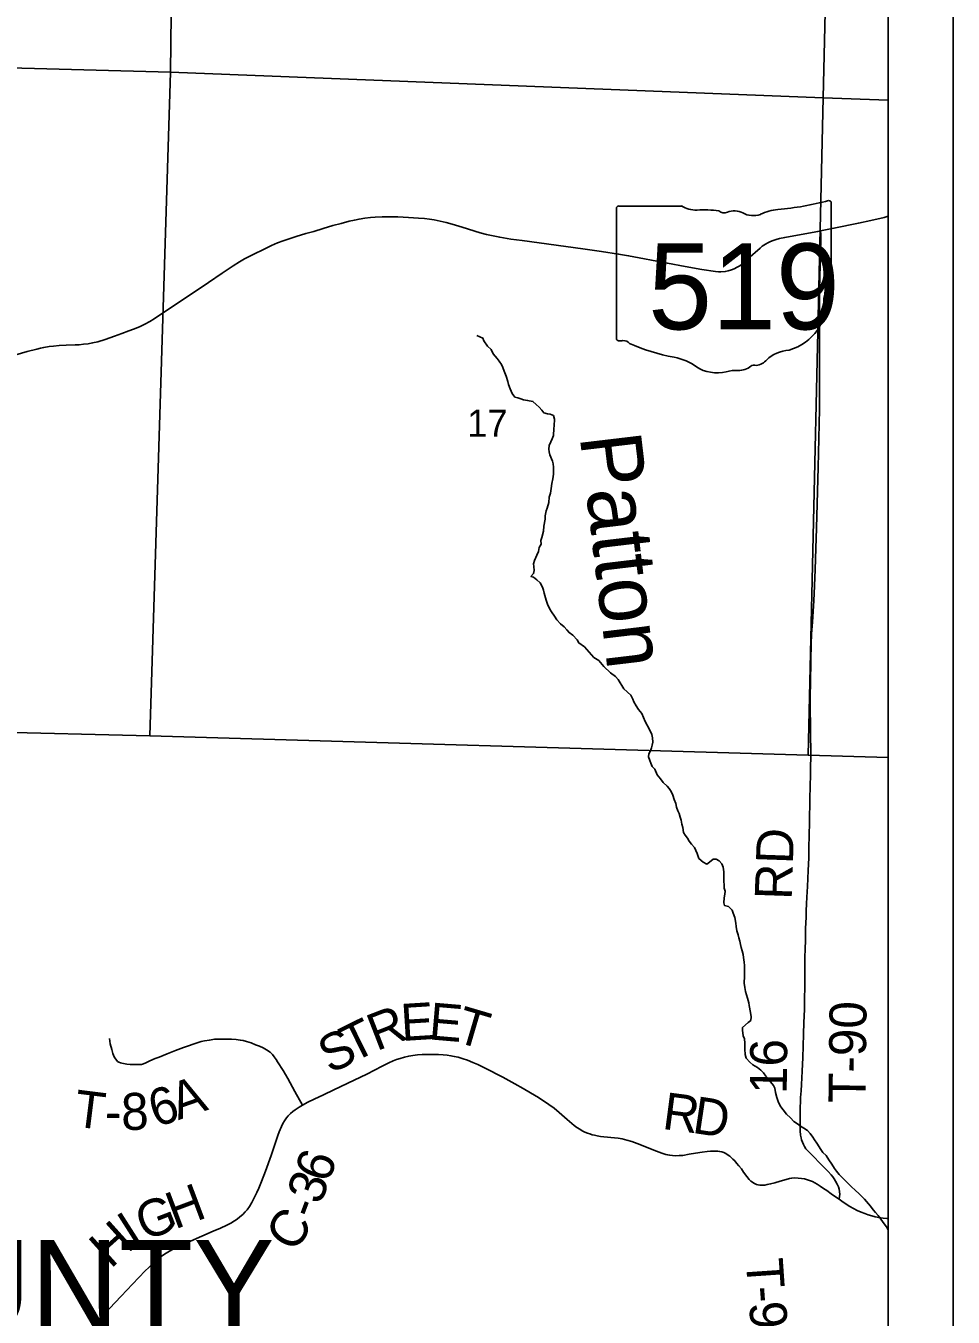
# Model space of a CAD drawing. Extents: x 0 to 34, y 0 to 22.
# Drawn here: x 8.076 to 9.5, y 16.635 to 18.617 of the extents above; entities that cross this region are included whole.
import ezdxf

# ---------------------------------------------------------------- set-up
doc = ezdxf.new("R2010")
doc.units = 0
for name, color, linetype in [('GM_X_Corporation', 7, 'Continuous'), ('GM_X_County_Road', 7, 'Continuous'), ('GM_X_County_Road_Text', 7, 'Continuous'), ('GM_X_Minor_River', 7, 'Continuous'), ('GM_X_Minor_River_Text', 7, 'Continuous'), ('GM_X_Section_Text', 7, 'Continuous'), ('GM_X_State_Location', 7, 'Continuous'), ('GM_X_State_Route', 7, 'Continuous'), ('GM_X_State_Shield', 7, 'Continuous'), ('GM_X_Township_Road', 7, 'Continuous'), ('GM_X_Township_Road_Text', 7, 'Continuous'), ('SH_Data', 7, 'Continuous'), ('SH_Text', 7, 'Continuous')]:
    doc.layers.add(name, color=color, linetype=linetype)

msp = doc.modelspace()

# ---------------------------------------------------------------- linework, layer by layer
at = {"layer": 'GM_X_Corporation'}
for points in [[(9.4, 16.4853), (9.4, 20.4), (2.6, 20.4), (2.6, 16.6918), (3.1555, 16.6686), (3.1684, 16.6682), (4.0515, 16.6368), (4.1011, 16.6362), (4.1867, 16.6352), (4.5473, 16.6256), (4.6351, 16.6229), (5.4202, 16.5982), (6.0834, 16.5816), (6.2194, 16.578), (8.0963, 16.5226), (9.09, 16.4927)], [(9.4, 16.4853), (9.4, 20.4), (6.2895, 20.4), (6.2595, 19.6124), (6.2942, 19.6131), (6.2926, 19.1539), (6.292, 18.5898), (6.2786, 18.5898), (6.2744, 18.4654), (6.2729, 18.2077), (6.2194, 16.578), (8.0963, 16.5226), (9.09, 16.4927)], [(8.2946, 19.5667), (8.3101, 19.5662), (8.2986, 18.5464), (7.291, 18.5737), (7.3046, 19.5855)], [(9.3157, 19.5601), (9.3252, 19.5587), (9.3006, 18.5069), (8.2986, 18.5464), (8.3101, 19.5662)], [(9.4, 18.5032), (9.4, 19.5563), (9.3252, 19.5587), (9.3006, 18.5069)], [(8.2986, 18.5464), (8.2669, 17.5271), (7.261, 17.5518), (7.291, 18.5737)], [(8.2986, 18.5464), (9.3006, 18.5069), (9.2775, 17.4976), (8.2669, 17.5271)], [(9.4, 17.4939), (9.4, 18.5032), (9.3006, 18.5069), (9.2775, 17.4976)]]:
    msp.add_lwpolyline(points, close=True, dxfattribs=at)
at = {"layer": 'GM_X_County_Road'}
msp.add_lwpolyline([(8.1832, 16.6253), (8.1961, 16.6386), (8.2229, 16.667), (8.2402, 16.6855), (8.2597, 16.7057), (8.2651, 16.711), (8.2723, 16.7179), (8.2779, 16.7229), (8.284, 16.7276), (8.2892, 16.7312), (8.2967, 16.7357), (8.3016, 16.7384), (8.3111, 16.743), (8.3289, 16.7513), (8.3467, 16.7589), (8.3641, 16.7665), (8.3752, 16.7713), (8.3851, 16.7758), (8.3912, 16.779), (8.3968, 16.7824), (8.4008, 16.7853), (8.4051, 16.7885), (8.4092, 16.7922), (8.4132, 16.7961), (8.4159, 16.7995), (8.4195, 16.8046), (8.4233, 16.8106), (8.427, 16.8177), (8.431, 16.8261), (8.4339, 16.8327), (8.4379, 16.8427), (8.444, 16.8586), (8.4528, 16.8827), (8.4591, 16.9014), (8.4633, 16.9136), (8.4653, 16.9191), (8.4687, 16.9273), (8.4709, 16.9318), (8.4735, 16.9362), (8.4767, 16.9406), (8.4793, 16.9437), (8.4827, 16.9473), (8.4862, 16.9503), (8.4899, 16.9531), (8.496, 16.9571), (8.5013, 16.9602), (8.5091, 16.9646), (8.5188, 16.9695), (8.5334, 16.9762), (8.5491, 16.9835), (8.5805, 16.9984), (8.5996, 17.0079), (8.6234, 17.0201), (8.6334, 17.0251), (8.6404, 17.0283), (8.6456, 17.0302), (8.6508, 17.032), (8.6574, 17.0339), (8.6641, 17.0354), (8.6707, 17.0365), (8.6774, 17.0373), (8.685, 17.0378), (8.693, 17.0379), (8.7097, 17.0377), (8.7172, 17.0373), (8.723, 17.0369), (8.7288, 17.0361), (8.7341, 17.035), (8.7401, 17.0336), (8.7479, 17.0314), (8.7542, 17.0293), (8.7628, 17.0257), (8.77, 17.0225), (8.7814, 17.017), (8.8084, 17.0029), (8.827, 16.9929), (8.8399, 16.9857), (8.8511, 16.9793), (8.8632, 16.9717), (8.879, 16.9612), (8.8872, 16.9553), (8.8952, 16.9487), (8.9072, 16.9382), (8.9181, 16.9291), (8.9224, 16.9259), (8.9267, 16.9231), (8.9306, 16.9209), (8.9345, 16.9189), (8.9385, 16.9172), (8.9423, 16.9159), (8.9458, 16.9148), (8.9496, 16.9138), (8.9536, 16.913), (8.9585, 16.9122), (8.9742, 16.9106), (8.9856, 16.9093), (8.992, 16.9083), (8.9989, 16.9066), (9.0066, 16.9042), (9.0151, 16.9012), (9.0266, 16.8968), (9.0403, 16.8911), (9.0529, 16.8863), (9.0589, 16.8844), (9.0617, 16.8838), (9.0649, 16.8832), (9.0693, 16.8827), (9.0741, 16.8825), (9.0792, 16.8826), (9.085, 16.883), (9.0946, 16.8847), (9.1046, 16.8866), (9.1144, 16.8881), (9.1222, 16.8892), (9.1273, 16.8895), (9.1321, 16.8897), (9.1356, 16.8895), (9.1386, 16.8893), (9.1413, 16.889), (9.1448, 16.8882), (9.148, 16.8872), (9.151, 16.8857), (9.1544, 16.8835), (9.1571, 16.8816), (9.1617, 16.8774), (9.1646, 16.8745), (9.1676, 16.8713), (9.1708, 16.8671), (9.1749, 16.8622), (9.1783, 16.8572), (9.1832, 16.8504), (9.187, 16.8461), (9.1894, 16.8436), (9.1917, 16.8417), (9.1939, 16.8403), (9.196, 16.8393), (9.1981, 16.8384), (9.2005, 16.8377), (9.203, 16.8373), (9.2107, 16.8374), (9.2146, 16.8381), (9.2197, 16.8393), (9.2263, 16.8411), (9.2342, 16.8435), (9.2437, 16.8462), (9.2486, 16.8475), (9.2522, 16.8482), (9.2567, 16.8485), (9.2618, 16.8482), (9.2673, 16.8477), (9.2716, 16.847), (9.2763, 16.8457), (9.2812, 16.8441), (9.2841, 16.8428), (9.2875, 16.8411), (9.2913, 16.8389), (9.2959, 16.8359), (9.301, 16.8323), (9.3059, 16.8289), (9.3128, 16.8239), (9.3224, 16.8171), (9.3248, 16.8156), (9.3291, 16.8125), (9.3342, 16.8091), (9.3412, 16.8046), (9.347, 16.8013), (9.3525, 16.7986), (9.3586, 16.7958), (9.3642, 16.7936), (9.3694, 16.7918), (9.3749, 16.79), (9.3805, 16.7886), (9.3858, 16.7875), (9.3927, 16.7865), (9.3984, 16.786), (9.4, 16.7859)], dxfattribs=at)
at = {"layer": 'GM_X_Minor_River'}
for points in [[(8.8199, 18.0599), (8.8174, 18.0666), (8.8161, 18.0715), (8.8135, 18.0797), (8.8109, 18.0871), (8.8088, 18.0927), (8.8064, 18.0975), (8.8032, 18.1023), (8.8, 18.1067), (8.794, 18.114), (8.7907, 18.1207), (8.7852, 18.1258), (8.7792, 18.1339), (8.7779, 18.138), (8.7733, 18.1401), (8.7689, 18.1418)], [(9.0381, 17.4803), (9.0357, 17.4852), (9.0344, 17.4896), (9.0323, 17.4949), (9.0329, 17.4994), (9.0354, 17.504), (9.0367, 17.5086), (9.0381, 17.5128), (9.0387, 17.5173), (9.0384, 17.5241), (9.0375, 17.5294), (9.0338, 17.5368), (9.0273, 17.5494), (9.0219, 17.5613), (9.0167, 17.5679), (9.0135, 17.5734), (9.0099, 17.5793), (9.0082, 17.5834), (9.0049, 17.5897), (8.9943, 17.5995), (8.9858, 17.6139), (8.9815, 17.6183), (8.9737, 17.6241), (8.9638, 17.6335), (8.9559, 17.643), (8.9485, 17.6477), (8.941, 17.6557), (8.9342, 17.6638), (8.9253, 17.6699), (8.9225, 17.6747), (8.9161, 17.682), (8.9103, 17.6859), (8.9067, 17.69), (8.9027, 17.6947), (8.8969, 17.6994), (8.8913, 17.7053), (8.8877, 17.7108), (8.8833, 17.7174), (8.8809, 17.7219), (8.8772, 17.7296), (8.875, 17.7356), (8.872, 17.7461), (8.8711, 17.7509), (8.8694, 17.7554), (8.8657, 17.7624), (8.8606, 17.7668), (8.8559, 17.7711), (8.8517, 17.7721), (8.8557, 17.7764), (8.8567, 17.7813), (8.8561, 17.787), (8.8556, 17.7911), (8.8573, 17.7964), (8.8608, 17.8045), (8.8632, 17.8102), (8.8645, 17.8166), (8.8673, 17.8216), (8.8671, 17.8273), (8.8685, 17.8319), (8.8712, 17.8414), (8.8717, 17.8493), (8.8735, 17.8599), (8.8737, 17.8648), (8.875, 17.8728), (8.8767, 17.877), (8.8791, 17.8853), (8.8799, 17.8937), (8.8816, 17.9001), (8.8828, 17.907), (8.8837, 17.9149), (8.8853, 17.9221), (8.8862, 17.9289), (8.8864, 17.9331), (8.8866, 17.9399), (8.886, 17.9447), (8.8851, 17.9492), (8.881, 17.9585), (8.8796, 17.9633), (8.8791, 17.9675), (8.8797, 17.9731), (8.8825, 17.9785), (8.8842, 17.9831), (8.8863, 17.9884), (8.8871, 17.999), (8.8873, 18.0035), (8.8877, 18.0137), (8.8863, 18.0189), (8.8813, 18.021), (8.8771, 18.0216), (8.8717, 18.0233), (8.8686, 18.0274), (8.8646, 18.0321), (8.8599, 18.0361), (8.8548, 18.0408), (8.8467, 18.0424), (8.8406, 18.0433), (8.836, 18.0447), (8.8314, 18.046), (8.8272, 18.0474), (8.8228, 18.0529), (8.8199, 18.0599)], [(9.2764, 16.9213), (9.2709, 16.9249), (9.2655, 16.9277), (9.2608, 16.9313), (9.2554, 16.9349), (9.2502, 16.9408), (9.2439, 16.9462), (9.2388, 16.9529), (9.2356, 16.9573), (9.2319, 16.964), (9.2294, 16.9718), (9.2272, 16.9797), (9.2262, 16.9861), (9.2241, 16.9902), (9.2197, 16.9961), (9.2169, 17.0005), (9.2122, 17.0045), (9.2086, 17.0097), (9.2047, 17.0141), (9.1996, 17.0177), (9.1926, 17.022), (9.1879, 17.0259), (9.182, 17.0325), (9.1806, 17.0378), (9.18, 17.0461), (9.18, 17.0552), (9.1794, 17.0619), (9.1777, 17.0664), (9.1766, 17.0754), (9.1768, 17.0796), (9.1853, 17.0871), (9.1894, 17.0903), (9.1899, 17.096), (9.1886, 17.1023), (9.187, 17.1132), (9.1865, 17.1174), (9.1843, 17.1245), (9.1813, 17.1346), (9.1799, 17.141), (9.1793, 17.1474), (9.1797, 17.1583), (9.1794, 17.167), (9.1795, 17.1746), (9.1793, 17.1795), (9.1783, 17.187), (9.1774, 17.1915), (9.176, 17.1971), (9.1743, 17.2024), (9.1734, 17.2069), (9.1724, 17.2117), (9.1707, 17.217), (9.1698, 17.2218), (9.1681, 17.2278), (9.1671, 17.2346), (9.1661, 17.2398), (9.1647, 17.2481), (9.1621, 17.2548), (9.1605, 17.2597), (9.1549, 17.2651), (9.1488, 17.2668), (9.1479, 17.2709), (9.1484, 17.2785), (9.1493, 17.2842), (9.1499, 17.2887), (9.1482, 17.2932), (9.1477, 17.3087), (9.1481, 17.3185), (9.1467, 17.3256), (9.1446, 17.3305), (9.1406, 17.3352), (9.136, 17.3377), (9.1314, 17.3376), (9.1259, 17.3332), (9.1218, 17.3304), (9.1164, 17.3333), (9.1097, 17.3391), (9.1068, 17.3465), (9.103, 17.3558), (9.0983, 17.3609), (9.0947, 17.3657), (9.0919, 17.3701), (9.0883, 17.3745), (9.0862, 17.379), (9.0852, 17.3865), (9.0835, 17.3914), (9.0825, 17.3978), (9.0808, 17.4022), (9.0795, 17.4082), (9.0774, 17.4123), (9.0754, 17.4175), (9.074, 17.4231), (9.0715, 17.4294), (9.0694, 17.4362), (9.0669, 17.4417), (9.0641, 17.4462), (9.0609, 17.4502), (9.0546, 17.4556), (9.0506, 17.4612), (9.0458, 17.4674), (9.0421, 17.4763), (9.0381, 17.4803)], [(9.4, 16.7683), (9.3996, 16.769), (9.3975, 16.7735), (9.3939, 16.7779), (9.3891, 16.7853), (9.3847, 16.7908), (9.3808, 16.7952), (9.3772, 16.7996), (9.3732, 16.8048), (9.37, 16.8088), (9.3641, 16.8158), (9.3555, 16.8238), (9.3495, 16.8297), (9.3437, 16.8348), (9.3393, 16.8391), (9.3354, 16.8432), (9.3318, 16.8472), (9.3251, 16.8538), (9.3208, 16.8589), (9.318, 16.863), (9.3139, 16.8693), (9.3091, 16.8763), (9.3051, 16.883), (9.3, 16.8873), (9.2968, 16.8921), (9.2907, 16.9017), (9.2871, 16.9069), (9.2843, 16.911), (9.2803, 16.9165), (9.2764, 16.9213)]]:
    msp.add_lwpolyline(points, dxfattribs=at)
at = {"layer": 'GM_X_State_Route'}
msp.add_lwpolyline([(8.0609, 18.1122), (8.0786, 18.1174), (8.0931, 18.1212), (8.0988, 18.1225), (8.1038, 18.1236), (8.1121, 18.1249), (8.1189, 18.1257), (8.1277, 18.1266), (8.138, 18.1271), (8.1521, 18.1274), (8.1582, 18.1278), (8.1648, 18.1285), (8.1718, 18.1294), (8.1788, 18.1306), (8.1867, 18.1324), (8.1979, 18.1358), (8.2122, 18.1407), (8.2239, 18.145), (8.2346, 18.1489), (8.2414, 18.1515), (8.251, 18.1555), (8.2588, 18.1592), (8.2669, 18.1637), (8.2731, 18.1675), (8.2816, 18.173), (8.3226, 18.2003), (8.3569, 18.2234), (8.3776, 18.2376), (8.3947, 18.2491), (8.4041, 18.2551), (8.4121, 18.2596), (8.422, 18.2646), (8.4451, 18.2761), (8.4537, 18.2803), (8.4628, 18.2841), (8.4716, 18.2875), (8.4819, 18.2909), (8.4914, 18.294), (8.5062, 18.2984), (8.5186, 18.3018), (8.5329, 18.3064), (8.5477, 18.3108), (8.5605, 18.3141), (8.5727, 18.3173), (8.5807, 18.3192), (8.5879, 18.3206), (8.597, 18.322), (8.6056, 18.3232), (8.6124, 18.3237), (8.6232, 18.3241), (8.6333, 18.3244), (8.6476, 18.3241), (8.664, 18.3233), (8.6793, 18.3223), (8.6883, 18.3216), (8.6962, 18.3206), (8.703, 18.3196), (8.7124, 18.3177), (8.7217, 18.3155), (8.7307, 18.313), (8.7462, 18.3081), (8.774, 18.2996), (8.7837, 18.2971), (8.7938, 18.2948), (8.804, 18.2929), (8.8211, 18.29), (8.8384, 18.2876), (8.9316, 18.2751), (8.9601, 18.2709), (8.9862, 18.2671), (9.0018, 18.2643), (9.0612, 18.2529), (9.0884, 18.2481), (9.114, 18.2435), (9.1351, 18.2402), (9.1397, 18.2397), (9.1435, 18.2396), (9.15, 18.2401), (9.1548, 18.2412), (9.1596, 18.2426), (9.1638, 18.2443), (9.1686, 18.2468), (9.1723, 18.2491), (9.1759, 18.2516), (9.1807, 18.2555), (9.185, 18.2595), (9.2035, 18.2762), (9.207, 18.2789), (9.2117, 18.2822), (9.2155, 18.2844), (9.2196, 18.2863), (9.2234, 18.2878), (9.2282, 18.2894), (9.2335, 18.2909), (9.2415, 18.2927), (9.2498, 18.2942), (9.292, 18.3018), (9.2965, 18.3026), (9.3169, 18.3066), (9.3546, 18.3146), (9.3736, 18.3186), (9.3941, 18.3233), (9.4, 18.325)], dxfattribs=at)
at = {"layer": 'GM_X_State_Shield'}
for p, q in [((9.3128, 18.2411), (9.3128, 18.3458)), ((8.9832, 18.3374), (8.9832, 18.1373)), ((9.083, 18.3408), (8.9865, 18.3408)), ((9.3128, 18.2411), (9.3128, 18.2411))]:
    msp.add_line(p, q, dxfattribs=at)
for centre, major_axis, start_param, end_param in [((9.1954, 18.6137), (0.3495, 0), 4.814394, 5.042369), ((9.3092, 18.3462), (0.00367, 0), 6.141152, 7.989035), ((8.987, 18.3378), (0.00382, 0), 1.712693, 3.28349), ((9.106, 18.3641), (0.037, 0), 4.042523, 4.731795), ((9.1183, 18.2285), (0.133, 0), 1.404758, 1.657858), ((9.1485, 18.3388), (0.0107, 0), 3.836095, 5.185415), ((9.1641, 18.3157), (0.0222, 0), 0.950623, 2.079405), ((9.1928, 18.3474), (0.0267, 0), 4.081561, 5.145723), ((9.24, 18.2797), (0.0703, 0), 1.699011, 2.107814), ((9.312, 18.2334), (0.00568, 0), 1.883978, 3.671073), ((9.2759, 18.2202), (0.0341, 0), 5.934695, 6.695948), ((9.3089, 18.2407), (0.00393, 0), 5.05454, 6.418171), ((9.326, 18.1973), (0.0248, 0), 2.387724, 3.262537), ((9.215, 18.184), (0.0874, 0), 5.101752, 6.440018), ((8.9871, 18.1368), (0.00385, 0), 3.00124, 4.508301), ((8.9876, 18.1573), (0.0294, 0), 4.665946, 4.897461), ((8.9937, 18.1257), (0.0106, 0), 0.519207, 1.627899), ((9.1275, 18.3055), (0.2524, 0), 4.195997, 4.488961), ((9.0522, 18.0474), (0.079, 0), 0.823519, 1.323587), ((9.1912, 18.1179), (0.0282, 0), 4.937069, 5.64225), ((9.2519, 18.0811), (0.0479, 0), 1.647645, 2.488434), ((9.1376, 18.1247), (0.0501, 0), 4.026481, 4.996735), ((9.1666, 18.0555), (0.0412, 0), 1.495662, 1.94098), ((9.1703, 18.1097), (0.0267, 0), 4.691044, 5.507374), ((9.1944, 18.0904), (0.00752, 0), 1.147584, 2.315152)]:
    msp.add_ellipse(centre, major_axis=major_axis, ratio=0.8, start_param=start_param, end_param=end_param, dxfattribs=at)
at = {"layer": 'GM_X_Township_Road'}
for points in [[(9.288, 17.7827), (9.2892, 17.8147), (9.2901, 17.8463), (9.2928, 17.9397), (9.2934, 17.9615), (9.2947, 18.0288), (9.295, 18.0651), (9.2949, 18.1018), (9.2949, 18.1386), (9.2947, 18.1749), (9.2948, 18.1947), (9.2949, 18.2129), (9.2952, 18.2317), (9.2968, 18.2893), (9.2967, 18.297), (9.2965, 18.3026)], [(9.3248, 16.8156), (9.3256, 16.82), (9.3259, 16.8233), (9.3252, 16.8313), (9.3239, 16.8348), (9.322, 16.8389), (9.3195, 16.8433), (9.3175, 16.8468), (9.3152, 16.8499), (9.3127, 16.853), (9.308, 16.858), (9.2982, 16.8681), (9.2827, 16.8841), (9.2793, 16.8874), (9.2763, 16.8904), (9.274, 16.8931), (9.2719, 16.8964), (9.2702, 16.8996), (9.2685, 16.9034), (9.2673, 16.9067), (9.2665, 16.9102), (9.2658, 16.9142), (9.2653, 16.9206), (9.2652, 16.9502), (9.2657, 16.9718), (9.2664, 16.9822), (9.2672, 16.9919), (9.2682, 17.0121), (9.2691, 17.0331), (9.2696, 17.0507), (9.2701, 17.0692), (9.2708, 17.0868), (9.2715, 17.107), (9.2719, 17.124), (9.2722, 17.1413), (9.2721, 17.1666), (9.2725, 17.1858), (9.2728, 17.2011), (9.2731, 17.2118), (9.2735, 17.2316), (9.2741, 17.249), (9.2745, 17.2584), (9.2749, 17.2695), (9.2753, 17.2796), (9.2762, 17.2961), (9.2772, 17.3203), (9.2782, 17.3398), (9.2784, 17.3554), (9.2789, 17.3745), (9.2796, 17.3944), (9.2801, 17.4311), (9.2808, 17.4679), (9.2814, 17.5061), (9.2811, 17.526), (9.2808, 17.5486), (9.2806, 17.5625), (9.2807, 17.5892), (9.2808, 17.6076), (9.2813, 17.6439), (9.2819, 17.6678), (9.2826, 17.6835), (9.284, 17.7024), (9.2859, 17.7345), (9.287, 17.7577), (9.288, 17.7827)], [(8.2048, 17.0625), (8.206, 17.0545), (8.2081, 17.0456), (8.2101, 17.0392), (8.212, 17.0343), (8.214, 17.031), (8.2159, 17.0287), (8.2172, 17.0274), (8.219, 17.0262), (8.2215, 17.0251), (8.2238, 17.0245), (8.2264, 17.0239), (8.2313, 17.0231), (8.2364, 17.0225), (8.2408, 17.0223), (8.2486, 17.0224), (8.2517, 17.0225), (8.2538, 17.0228), (8.2554, 17.0232), (8.2593, 17.0246), (8.2669, 17.0281), (8.275, 17.0317), (8.2808, 17.034), (8.2931, 17.039), (8.3061, 17.0439), (8.3186, 17.0486), (8.3407, 17.0563), (8.3457, 17.0577), (8.3504, 17.0587), (8.3581, 17.0601), (8.3662, 17.0612), (8.3705, 17.0616), (8.3745, 17.0617), (8.3918, 17.0613), (8.3994, 17.0607), (8.4054, 17.06), (8.41, 17.0592), (8.4153, 17.0577), (8.422, 17.0556), (8.429, 17.0529), (8.4349, 17.0506), (8.4405, 17.0481), (8.4459, 17.0452), (8.4514, 17.0414), (8.4548, 17.0378), (8.4574, 17.0343), (8.4605, 17.0304), (8.4628, 17.0268), (8.4715, 17.0132), (8.4785, 17.0011), (8.4893, 16.9812), (8.5013, 16.9602)]]:
    msp.add_lwpolyline(points, dxfattribs=at)
at = {"layer": 'SH_Data'}
for points in [[(2.5, 20.5), (9.5, 20.5), (9.5, 13.5), (2.5, 13.5)], [(2.6, 20.4), (9.4, 20.4), (9.4, 13.6), (2.6, 13.6)]]:
    msp.add_lwpolyline(points, close=True, dxfattribs=at)

# ---------------------------------------------------------------- texts
at = {"layer": 'GM_X_County_Road_Text'}
for s, rotation, p in [('E', 3.5873, (8.6536, 17.0586)), ('E', 355.1321, (8.6938, 17.0613)), ('T', 26.2181, (8.5777, 17.0245)), ('R', 21.2075, (8.6146, 17.0427)), ('T', 343.5984, (8.7332, 17.0583)), ('S', 26.3589, (8.5434, 17.0075)), ('R', 352.5361, (9.052, 16.9238)), ('D', 351.4462, (9.098, 16.9178)), ('6', 70.4006, (8.5409, 16.8388)), ('3', 70.1946, (8.5289, 16.8057)), ('H', 20.6294, (8.3051, 16.769)), ('G', 21.1124, (8.2586, 16.751)), ('I', 32.482, (8.2416, 16.7398)), ('C', 56.5167, (8.4884, 16.7317)), ('-', 69.451, (8.5205, 16.7831)), ('H', 42.0365, (8.2064, 16.7079))]:
    msp.add_text(s, height=0.0568, rotation=rotation, dxfattribs=at).set_placement(p)
at = {"layer": 'GM_X_Minor_River_Text'}
msp.add_text('Patton', height=0.09397, rotation=276.791, dxfattribs=at).set_placement((8.9265, 17.9875))
at = {"layer": 'GM_X_Section_Text'}
msp.add_text('17', height=0.04186, rotation=0, dxfattribs=at).set_placement((8.7537, 17.9864))
at = {"layer": 'GM_X_State_Location'}
for s in ['s', 'r']:
    msp.add_text(s, height=0.000189, dxfattribs=at).set_placement((9.1443, 18.224))
msp.add_text('519', height=0.000189, rotation=0, dxfattribs=at).set_placement((9.0775, 18.2102))
at = {"layer": 'GM_X_State_Shield'}
msp.add_text('519', height=0.13184, dxfattribs=at).set_placement((9.0317, 18.1514))
at = {"layer": 'GM_X_Township_Road_Text'}
for s, height, rotation, p in [('RD', 0.05682, 88.0242, (9.252, 17.2749)), ('T-90', 0.05682, 89.3094, (9.3653, 16.9633)), ('16', 0.05682, 89.3101, (9.2444, 16.9769)), ('A', 0.0568, 19.1773, (8.3103, 16.9369)), ('T', 0.0568, 352.833, (8.1484, 16.9277)), ('8', 0.0568, 1.5726, (8.2233, 16.9216)), ('6', 0.0568, 18.1088, (8.2759, 16.9256)), ('-', 0.0568, 359.2933, (8.1975, 16.9219)), ('T', 0.0568, 273.9287, (9.1816, 16.7232)), ('-', 0.0568, 274.1056, (9.1845, 16.6806)), ('9', 0.0568, 274.9285, (9.1863, 16.6565))]:
    msp.add_text(s, height=height, rotation=rotation, dxfattribs=at).set_placement(p)
at = {"layer": 'SH_Text'}
msp.add_text('HARRISON COUNTY', height=0.14, dxfattribs=at).set_placement((6.6276, 16.6131))

doc.saveas('drawing.dxf')
